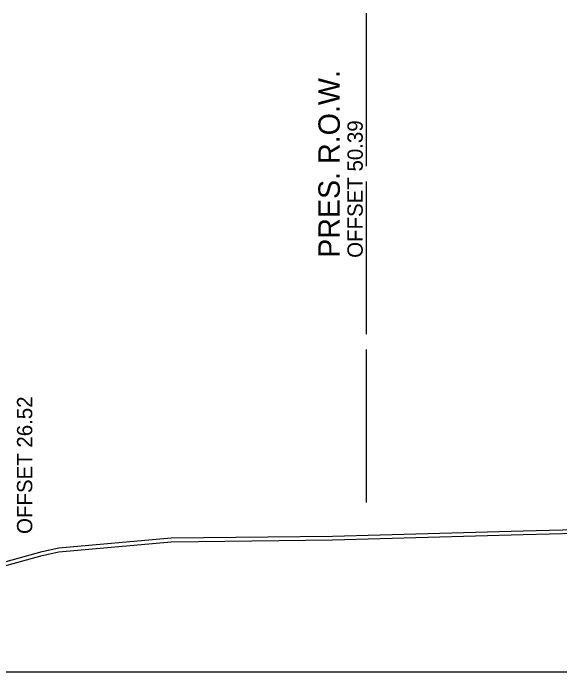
# Model space of a CAD drawing. Extents: x 1574 to 14903, y 7971 to 16537.
# Drawn here: x 13027.27 to 13063.03, y 8000 to 8043.07 of the extents above; entities that cross this region are included whole.
import ezdxf

# ---------------------------------------------------------------- set-up
doc = ezdxf.new("R2010")
doc.units = 0
for name, color, linetype in [('DESIGN - SHEET - Light Grid', 7, 'Continuous'), ('DESIGN - TYPICAL - Slope Tie Text', 7, 'Continuous'), ('SURVEY - GROUND - Bottom of Topsoil Layer', 7, 'Continuous'), ('SURVEY - GROUND - Top of Ground', 7, 'Continuous'), ('SURVEY - PROPERTY - ROW Lines', 7, 'Continuous'), ('SURVEY - PROPERTY - ROW Lines Text', 7, 'Continuous')]:
    doc.layers.add(name, color=color, linetype=linetype)

msp = doc.modelspace()

# ---------------------------------------------------------------- linework, layer by layer
at = {"layer": 'DESIGN - SHEET - Light Grid'}
msp.add_line((13000, 8000), (13300, 8000), dxfattribs=at)
at = {"layer": 'SURVEY - GROUND - Bottom of Topsoil Layer'}
for p, q in [((13048.155, 8008.628), (13060.645, 8008.981)), ((13060.645, 8008.981), (13067.496, 8009.15)), ((13030.247, 8007.853), (13037.605, 8008.503)), ((13037.605, 8008.503), (13048.155, 8008.628)), ((13025.223, 8006.533), (13029.155, 8007.614)), ((13029.155, 8007.614), (13030.247, 8007.853))]:
    msp.add_line(p, q, dxfattribs=at)
at = {"layer": 'SURVEY - GROUND - Top of Ground'}
msp.add_lwpolyline([(13025.223, 8006.783), (13029.155, 8007.864), (13030.247, 8008.103), (13037.605, 8008.753), (13048.155, 8008.878), (13060.645, 8009.231), (13067.496, 8009.4)], dxfattribs=at)
at = {"layer": 'SURVEY - PROPERTY - ROW Lines'}
for p, q in [((13050.389, 8033.072), (13050.389, 8043.072)), ((13050.389, 8022.072), (13050.389, 8032.072)), ((13050.389, 8011.072), (13050.389, 8021.072))]:
    msp.add_line(p, q, dxfattribs=at)

# ---------------------------------------------------------------- texts
at = {"layer": 'DESIGN - TYPICAL - Slope Tie Text'}
msp.add_text('OFFSET 26.52', height=1, rotation=90, dxfattribs=at).set_placement((13028.519, 8009.016))
at = {"layer": 'SURVEY - PROPERTY - ROW Lines Text'}
for s, height, p in [('PRES. R.O.W.', 1.4, (13048.639, 8027.072)), ('OFFSET 50.39', 1, (13050.139, 8027.072))]:
    msp.add_text(s, height=height, rotation=90, dxfattribs=at).set_placement(p)

doc.saveas('drawing.dxf')
